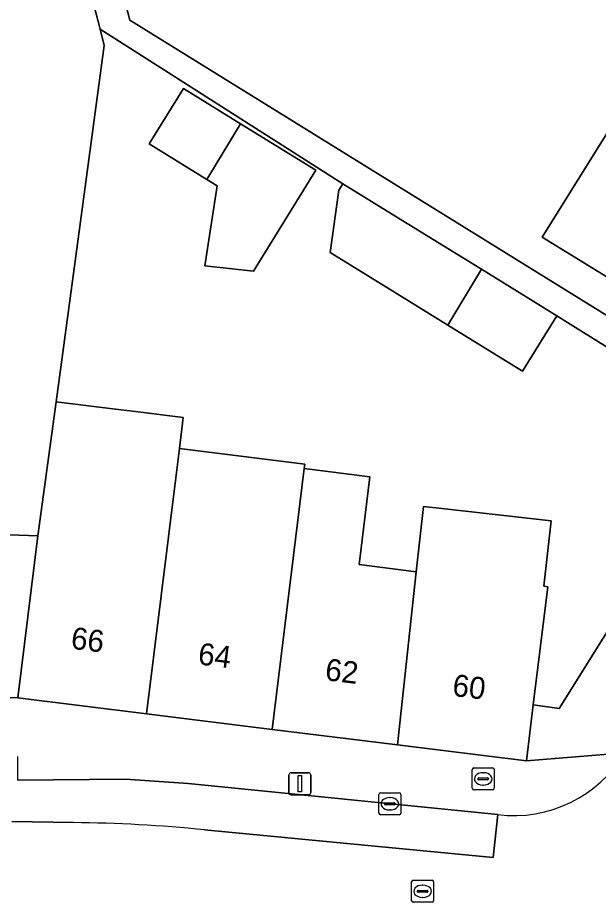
# Model space of a CAD drawing. Extents: x 160856 to 161310, y 384024 to 384878.
# Drawn here: x 161108.31 to 161134.7, y 384419.02 to 384459.26 of the extents above; entities that cross this region are included whole.
import ezdxf

# ---------------------------------------------------------------- set-up
doc = ezdxf.new("R2010")
doc.units = 0
for name, color, linetype in [('IMGEO_Brandkraan', 7, 'Continuous'), ('IMGEO_Erf', 7, 'Continuous'), ('IMGEO_Kolk', 7, 'Continuous'), ('IMGEO_Lichtmast', 7, 'Continuous'), ('IMGEO_Pand', 7, 'Continuous'), ('IMGEO_Pand_nummerreeks', 7, 'Continuous'), ('IMGEO_Parkeervlak_open', 7, 'Continuous'), ('IMGEO_Rijbaan_lokaal_open', 7, 'Continuous'), ('IMGEO_Rioolput', 7, 'Continuous'), ('IMGEO_Voetpad_open', 7, 'Continuous')]:
    doc.layers.add(name, color=color, linetype=linetype)

msp = doc.modelspace()

# ---------------------------------------------------------------- linework, layer by layer
at = {"layer": 'IMGEO_Brandkraan'}
for p, q in [((161128.969, 384424.207), (161128.969, 384425.059)), ((161129.044, 384425.133), (161129.896, 384425.133)), ((161129.457, 384424.913), (161129.482, 384424.913)), ((161129.97, 384425.059), (161129.97, 384424.207)), ((161129.228, 384424.627), (161129.228, 384424.639)), ((161129.666, 384424.59), (161129.268, 384424.59)), ((161129.271, 384424.676), (161129.669, 384424.676)), ((161129.712, 384424.639), (161129.712, 384424.627)), ((161129.896, 384424.133), (161129.044, 384424.133)), ((161129.48, 384424.353), (161129.455, 384424.353))]:
    msp.add_line(p, q, dxfattribs=at)
for points in [[(161128.969, 384424.207), (161128.969, 384425.059)], [(161129.044, 384425.133), (161129.896, 384425.133)], [(161129.97, 384425.059), (161129.97, 384424.207)], [(161129.896, 384424.133), (161129.044, 384424.133)]]:
    msp.add_lwpolyline(points, dxfattribs=at)
for centre, radius, start, end in [((161129.046, 384425.057), 0.0765, 91.552, 178.448), ((161129.046, 384425.057), 0.0765, 91.552, 178.448), ((161129.894, 384425.057), 0.0765, 1.552, 88.448), ((161129.894, 384425.057), 0.0765, 1.552, 88.448), ((161129.268, 384424.636), 0.0403, 85.8775, 175.7526), ((161129.265, 384424.626), 0.0366, 178.938, 274.7102), ((161129.669, 384424.633), 0.043, 264.8664, 352.4533), ((161129.673, 384424.638), 0.0386, 1.7309, 96.639), ((161129.046, 384424.209), 0.0765, 181.552, 268.448), ((161129.046, 384424.209), 0.0765, 181.552, 268.448), ((161129.894, 384424.209), 0.0765, 271.552, 358.448), ((161129.894, 384424.209), 0.0765, 271.552, 358.448)]:
    msp.add_arc(centre, radius, start, end, dxfattribs=at)
for centre, major_axis, ratio, start_param, end_param in [((161129.456, 384424.633), (-0.387, 0.002), 0.722429, 4.712389, 7.853982), ((161129.481, 384424.633), (-0.39, 0.002), 0.717154, 1.570796, 4.712389)]:
    msp.add_ellipse(centre, major_axis=major_axis, ratio=ratio, start_param=start_param, end_param=end_param, dxfattribs=at)
at = {"layer": 'IMGEO_Erf'}
msp.add_lwpolyline([(161113.009, 384460.72), (161113.412, 384459.149), (161141.582, 384441.69), (161142.348, 384442.916), (161138.114, 384445.575), (161135.533, 384447.195), (161132.153, 384449.275), (161135.399, 384454.481), (161135.585, 384454.365), (161136.955, 384456.548), (161140.152, 384454.555), (161142.042, 384457.567), (161144.625, 384455.944), (161148.859, 384453.285), (161149.536, 384454.494), (161141.361, 384459.621)], dxfattribs=at)
for points in [[(161132.818, 384445.698), (161131.262, 384443.178), (161127.864, 384445.276), (161125.244, 384446.893), (161122.512, 384448.579), (161122.905, 384451.418), (161123.094, 384451.701), (161112.06, 384458.73), (161112.248, 384457.995), (161110.917, 384448.182), (161110.053, 384441.789), (161112.756, 384441.455), (161113.668, 384441.342), (161115.835, 384441.074), (161115.661, 384439.665), (161121.362, 384438.943), (161121.339, 384438.755), (161124.323, 384438.378), (161123.828, 384434.378), (161126.428, 384434.049), (161126.756, 384437.024), (161127.591, 384436.93), (161132.56, 384436.374), (161132.231, 384433.392), (161132.41, 384433.372), (161131.747, 384428.009), (161132.927, 384427.83), (161140.923, 384440.635)], [(161120.307, 384449.796), (161119.026, 384447.722), (161116.818, 384447.966), (161117.382, 384451.602), (161116.909, 384451.894), (161114.289, 384453.511), (161115.845, 384456.031), (161118.44, 384454.429), (161121.863, 384452.316)], [(161102.025, 384428.239), (161106.917, 384428.332), (161108.316, 384428.314), (161109.228, 384435.688), (161099.363, 384436.033)]]:
    msp.add_lwpolyline(points, close=True, dxfattribs=at)
at = {"layer": 'IMGEO_Kolk'}
for p, q in [((161124.727, 384423.076), (161124.727, 384423.928)), ((161124.802, 384424.002), (161125.654, 384424.002)), ((161125.215, 384423.782), (161125.24, 384423.782)), ((161125.728, 384423.928), (161125.728, 384423.076)), ((161124.986, 384423.496), (161124.986, 384423.508)), ((161125.424, 384423.459), (161125.026, 384423.459)), ((161125.029, 384423.545), (161125.427, 384423.545)), ((161125.47, 384423.508), (161125.47, 384423.496)), ((161125.654, 384423.002), (161124.802, 384423.002)), ((161125.238, 384423.222), (161125.213, 384423.222))]:
    msp.add_line(p, q, dxfattribs=at)
for points in [[(161124.727, 384423.076), (161124.727, 384423.928)], [(161124.802, 384424.002), (161125.654, 384424.002)], [(161125.728, 384423.928), (161125.728, 384423.076)], [(161125.654, 384423.002), (161124.802, 384423.002)]]:
    msp.add_lwpolyline(points, dxfattribs=at)
for centre, radius, start, end in [((161124.804, 384423.926), 0.0765, 91.552, 178.448), ((161124.804, 384423.926), 0.0765, 91.552, 178.448), ((161125.652, 384423.926), 0.0765, 1.552, 88.448), ((161125.652, 384423.926), 0.0765, 1.552, 88.448), ((161125.026, 384423.505), 0.0403, 85.8775, 175.7526), ((161125.023, 384423.495), 0.0366, 178.938, 274.7102), ((161125.427, 384423.502), 0.043, 264.8664, 352.4533), ((161125.431, 384423.507), 0.0386, 1.7309, 96.639), ((161124.804, 384423.078), 0.0765, 181.552, 268.448), ((161124.804, 384423.078), 0.0765, 181.552, 268.448), ((161125.652, 384423.078), 0.0765, 271.552, 358.448), ((161125.652, 384423.078), 0.0765, 271.552, 358.448)]:
    msp.add_arc(centre, radius, start, end, dxfattribs=at)
for centre, major_axis, ratio, start_param, end_param in [((161125.214, 384423.502), (-0.387, 0.002), 0.722429, 4.712389, 7.853982), ((161125.239, 384423.502), (-0.39, 0.002), 0.717154, 1.570796, 4.712389)]:
    msp.add_ellipse(centre, major_axis=major_axis, ratio=ratio, start_param=start_param, end_param=end_param, dxfattribs=at)
at = {"layer": 'IMGEO_Lichtmast'}
for p, q in [((161120.741, 384424.914), (161121.531, 384424.914)), ((161121.531, 384424.914), (161120.741, 384424.914)), ((161120.641, 384424.014), (161120.641, 384424.814)), ((161120.641, 384424.814), (161120.641, 384424.014)), ((161121.631, 384424.814), (161121.631, 384424.014)), ((161121.631, 384424.014), (161121.631, 384424.814)), ((161121.531, 384423.914), (161120.741, 384423.914)), ((161120.741, 384423.914), (161121.531, 384423.914))]:
    msp.add_line(p, q, dxfattribs=at)
msp.add_lwpolyline([(161121.061, 384424.789), (161121.211, 384424.789), (161121.211, 384424.039), (161121.061, 384424.039), (161121.061, 384424.789)], dxfattribs=at)
for centre, start, end in [((161120.741, 384424.814), 90, 180), ((161120.741, 384424.814), 90, 180), ((161121.531, 384424.814), 0, 90), ((161121.531, 384424.814), 360, 90), ((161120.741, 384424.014), 180, 270), ((161120.741, 384424.014), 180, 270), ((161121.531, 384424.014), 270, 0), ((161121.531, 384424.014), 270, 0)]:
    msp.add_arc(centre, 0.1, start, end, dxfattribs=at)
at = {"layer": 'IMGEO_Pand'}
for points in [[(161112.248, 384457.995), (161112.06, 384458.73), (161111.639, 384460.369), (161110.685, 384464.086), (161109.942, 384465.677), (161107.881, 384470.092), (161106.522, 384469.213), (161098.067, 384463.739), (161097.209, 384465.039), (161091.365, 384462.502), (161095.906, 384452.045), (161094.201, 384451.035), (161094.568, 384450.014), (161097.341, 384442.312), (161099.363, 384436.033), (161109.228, 384435.688), (161110.053, 384441.789), (161110.917, 384448.182)], [(161116.909, 384451.894), (161118.44, 384454.429), (161115.845, 384456.031), (161114.289, 384453.511)], [(161121.863, 384452.316), (161118.44, 384454.429), (161116.909, 384451.894), (161117.382, 384451.602), (161116.818, 384447.966), (161119.026, 384447.722), (161120.307, 384449.796)], [(161145.604, 384448.101), (161138.782, 384452.372), (161135.585, 384454.365), (161135.399, 384454.481), (161132.153, 384449.275), (161135.533, 384447.195), (161138.114, 384445.575), (161142.348, 384442.916)], [(161126.8, 384449.413), (161123.094, 384451.701), (161122.905, 384451.418), (161122.512, 384448.579), (161125.244, 384446.893), (161127.864, 384445.276), (161129.395, 384447.811)], [(161127.864, 384445.276), (161131.262, 384443.178), (161132.818, 384445.698), (161129.395, 384447.811)], [(161115.494, 384438.32), (161115.661, 384439.665), (161115.835, 384441.074), (161113.668, 384441.342), (161112.756, 384441.455), (161110.053, 384441.789), (161109.228, 384435.688), (161108.316, 384428.314), (161114.167, 384427.59)], [(161119.871, 384426.885), (161121.339, 384438.755), (161121.362, 384438.943), (161115.661, 384439.665), (161115.494, 384438.32), (161114.167, 384427.59)], [(161124.323, 384438.378), (161121.339, 384438.755), (161119.871, 384426.885), (161125.576, 384426.179), (161126.428, 384434.049), (161123.828, 384434.378)], [(161126.428, 384434.049), (161125.576, 384426.179), (161131.431, 384425.455), (161131.747, 384428.009), (161132.41, 384433.372), (161132.231, 384433.392), (161132.56, 384436.374), (161127.591, 384436.93), (161126.756, 384437.024)]]:
    msp.add_lwpolyline(points, close=True, dxfattribs=at)
at = {"layer": 'IMGEO_Parkeervlak_open'}
for points in [[(161116.807, 384422.313), (161129.927, 384421.062), (161130.131, 384423.013), (161116.057, 384424.417), (161113.205, 384424.617), (161108.306, 384424.573)], [(161108.046, 384422.701), (161110.83, 384422.646)]]:
    msp.add_lwpolyline(points, dxfattribs=at)
msp.add_arc((161110.187, 384357.306), 65.343, 84.1857, 89.43659, dxfattribs=at)
at = {"layer": 'IMGEO_Rijbaan_lokaal_open'}
for points in [[(161130.131, 384423.013), (161129.927, 384421.062), (161116.807, 384422.313)], [(161110.83, 384422.646), (161108.046, 384422.701)]]:
    msp.add_lwpolyline(points, dxfattribs=at)
for centre, radius, start, end in [((161130.875, 384428.802), 5.837, 262.6793, 329.2753), ((161110.187, 384357.306), 65.343, 84.1857, 89.43659)]:
    msp.add_arc(centre, radius, start, end, dxfattribs=at)
at = {"layer": 'IMGEO_Rioolput'}
for p, q in [((161126.217, 384419.094), (161126.217, 384419.946)), ((161126.292, 384420.02), (161127.144, 384420.02)), ((161126.705, 384419.8), (161126.73, 384419.8)), ((161127.218, 384419.946), (161127.218, 384419.094)), ((161126.476, 384419.514), (161126.476, 384419.526)), ((161126.914, 384419.477), (161126.516, 384419.477)), ((161126.519, 384419.563), (161126.917, 384419.563)), ((161126.728, 384419.24), (161126.703, 384419.24)), ((161126.96, 384419.526), (161126.96, 384419.514)), ((161127.144, 384419.02), (161126.292, 384419.02))]:
    msp.add_line(p, q, dxfattribs=at)
for points in [[(161126.217, 384419.094), (161126.217, 384419.946)], [(161126.292, 384420.02), (161127.144, 384420.02)], [(161127.218, 384419.946), (161127.218, 384419.094)], [(161127.144, 384419.02), (161126.292, 384419.02)]]:
    msp.add_lwpolyline(points, dxfattribs=at)
for centre, radius, start, end in [((161126.294, 384419.944), 0.0765, 91.552, 178.448), ((161126.294, 384419.944), 0.0765, 91.552, 178.448), ((161127.142, 384419.944), 0.0765, 1.552, 88.448), ((161127.142, 384419.944), 0.0765, 1.552, 88.448), ((161126.516, 384419.523), 0.0403, 85.8775, 175.7526), ((161126.513, 384419.513), 0.0366, 178.938, 274.7102), ((161126.917, 384419.52), 0.043, 264.8664, 352.4533), ((161126.921, 384419.525), 0.0386, 1.7309, 96.639), ((161126.294, 384419.096), 0.0765, 181.552, 268.448), ((161126.294, 384419.096), 0.0765, 181.552, 268.448), ((161127.142, 384419.096), 0.0765, 271.552, 358.448), ((161127.142, 384419.096), 0.0765, 271.552, 358.448)]:
    msp.add_arc(centre, radius, start, end, dxfattribs=at)
for centre, major_axis, ratio, start_param, end_param in [((161126.704, 384419.52), (-0.387, 0.002), 0.722429, 4.712389, 7.853982), ((161126.729, 384419.52), (-0.39, 0.002), 0.717154, 1.570796, 4.712389)]:
    msp.add_ellipse(centre, major_axis=major_axis, ratio=ratio, start_param=start_param, end_param=end_param, dxfattribs=at)
at = {"layer": 'IMGEO_Voetpad_open'}
for points in [[(161143.667, 384466.665), (161143.911, 384466.515), (161146.346, 384465.016), (161149.442, 384463.074), (161153.416, 384460.726), (161152.548, 384459.295), (161149.536, 384454.494), (161148.859, 384453.285), (161145.604, 384448.101), (161142.348, 384442.916), (161141.582, 384441.69), (161140.923, 384440.635), (161132.927, 384427.83), (161131.747, 384428.009), (161131.431, 384425.455), (161135.892, 384425.82), (161145.898, 384441.958), (161156.12, 384458.453)], [(161114.167, 384427.59), (161108.316, 384428.314), (161106.917, 384428.332), (161102.025, 384428.239), (161102.043, 384427.734), (161102.539, 384425.039), (161103.986, 384425.26)], [(161135.892, 384425.82), (161131.431, 384425.455), (161125.576, 384426.179), (161119.871, 384426.885), (161114.167, 384427.59)], [(161108.301, 384425.657), (161108.306, 384424.573), (161113.205, 384424.617), (161116.057, 384424.417), (161130.131, 384423.013)]]:
    msp.add_lwpolyline(points, dxfattribs=at)
msp.add_lwpolyline([(161113.412, 384459.149), (161113.009, 384460.72), (161111.639, 384460.369), (161112.06, 384458.73), (161123.094, 384451.701), (161126.8, 384449.413), (161129.395, 384447.811), (161132.818, 384445.698), (161140.923, 384440.635), (161141.582, 384441.69)], close=True, dxfattribs=at)
msp.add_arc((161130.875, 384428.802), 5.837, 262.6793, 329.2753, dxfattribs=at)

# ---------------------------------------------------------------- texts
at = {"layer": 'IMGEO_Pand_nummerreeks'}
for s, rotation, p in [('66', 352.9469, (161110.695, 384430.559)), ('64', 352.9491, (161116.473, 384429.844)), ('62', 352.9491, (161122.249, 384429.129)), ('60', 352.9491, (161128.034, 384428.414))]:
    msp.add_text(s, height=1, rotation=rotation, dxfattribs=at).set_placement(p)

doc.saveas('drawing.dxf')
